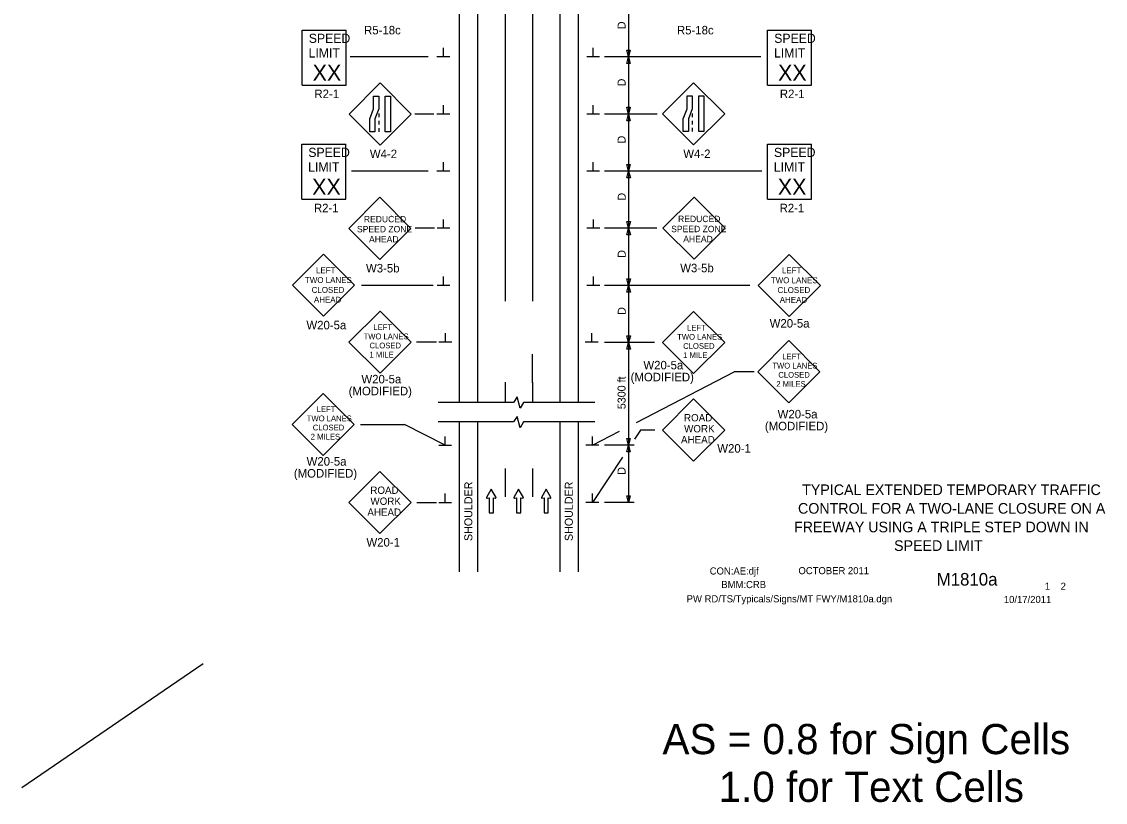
# Model space of a CAD drawing. Extents: x 16489 to 18480, y 5759 to 7026.
# Drawn here: x 16489 to 17437, y 5759 to 6442 of the extents above; entities that cross this region are included whole.
import ezdxf

# ---------------------------------------------------------------- set-up
doc = ezdxf.new("R2010")
doc.units = 0
for name, color, linetype in [('ALI_LEGAL_EX', 7, 'Continuous'), ('BORDER', 7, 'Continuous'), ('BORDER_SIGNAL_WO', 7, 'Continuous'), ('MT_SCRATCH_LEVEL_E', 7, 'Continuous'), ('PAVT_EDGE_EX', 7, 'Continuous'), ('TRAFFIC_SIGNS_PR', 7, 'Continuous'), ('TYPICAL_TEXT_DIMEN_PR', 7, 'Continuous')]:
    doc.layers.add(name, color=color, linetype=linetype)

msp = doc.modelspace()

# ---------------------------------------------------------------- linework, layer by layer
at = {"layer": 'ALI_LEGAL_EX'}
for p, q in [((16911.66, 7026.35), (16911.66, 6197.16)), ((16935.66, 7026.35), (16935.66, 6197.16)), ((16935.66, 7026.35), (16935.66, 6197.16))]:
    msp.add_line(p, q, dxfattribs=at)
for points in [[(16911.66, 6426.35), (16911.66, 6401.35)], [(16935.66, 6426.35), (16935.66, 6401.35)], [(16911.66, 6326.35), (16911.66, 6301.35)], [(16935.66, 6326.35), (16935.66, 6301.35)], [(16911.66, 6226.35), (16911.66, 6201.35)], [(16935.66, 6226.35), (16935.66, 6201.35)], [(16935.66, 6125.91), (16935.66, 6150.91)], [(16911.66, 6126.35), (16911.66, 6108.7)], [(16935.66, 6126.35), (16935.66, 6108.7)], [(16911.66, 6050.91), (16911.66, 6025.91)], [(16935.66, 6050.91), (16935.66, 6025.91)]]:
    msp.add_lwpolyline(points, dxfattribs=at)
at = {"layer": 'MT_SCRATCH_LEVEL_E'}
for p, q in [((16899.66, 6032.81), (16895.55, 6025.57)), ((16903.81, 6025.57), (16899.66, 6032.81)), ((16923.57, 6032.81), (16919.46, 6025.57)), ((16927.71, 6025.57), (16923.57, 6032.81)), ((16947.62, 6032.81), (16943.51, 6025.57)), ((16951.77, 6025.57), (16947.62, 6032.81)), ((16896.03, 6024.89), (16897.81, 6025.2)), ((16897.81, 6025.2), (16897.81, 6011.94)), ((16901.55, 6011.94), (16901.55, 6025.2)), ((16901.55, 6025.2), (16903.33, 6024.89)), ((16919.94, 6024.89), (16921.72, 6025.2)), ((16921.72, 6025.2), (16921.72, 6011.94)), ((16925.46, 6011.94), (16925.46, 6025.2)), ((16925.46, 6025.2), (16927.24, 6024.89)), ((16943.99, 6024.89), (16945.77, 6025.2)), ((16945.77, 6025.2), (16945.77, 6011.94)), ((16949.51, 6011.94), (16949.51, 6025.2)), ((16949.51, 6025.2), (16951.29, 6024.89)), ((16897.81, 6011.94), (16901.55, 6011.94)), ((16921.72, 6011.94), (16925.46, 6011.94)), ((16945.77, 6011.94), (16949.51, 6011.94))]:
    msp.add_line(p, q, dxfattribs=at)
for centre, start, end in [((16895.96, 6025.34), 150.42484, 279.96381), ((16903.4, 6025.34), 260.03619, 29.77312), ((16919.86, 6025.34), 150.42484, 279.96381), ((16927.3, 6025.34), 260.03619, 29.77312), ((16943.92, 6025.34), 150.42484, 279.96381), ((16951.36, 6025.34), 260.03619, 29.77312)]:
    msp.add_arc(centre, 0.463, start, end, dxfattribs=at)
at = {"layer": 'PAVT_EDGE_EX'}
for p, q in [((16871.66, 6926.66), (16871.66, 6108.7)), ((16887.66, 6926.66), (16887.66, 6108.7)), ((16959.66, 6926.66), (16959.66, 6108.7)), ((16975.66, 6926.66), (16975.66, 6108.7)), ((16871.66, 6091.58), (16871.66, 5960.31)), ((16887.66, 6091.58), (16887.66, 5960.31)), ((16959.66, 6091.58), (16959.66, 5960.31)), ((16975.66, 6091.58), (16975.66, 5960.31))]:
    msp.add_line(p, q, dxfattribs=at)
at = {"layer": 'TRAFFIC_SIGNS_PR'}
for p, q in [((16734.27, 6434.49), (16772.71, 6434.49)), ((16734.27, 6386.43), (16734.27, 6434.49)), ((16772.71, 6386.43), (16772.71, 6434.49)), ((17141.33, 6434.49), (17179.77, 6434.49)), ((17141.33, 6386.43), (17141.33, 6434.49)), ((17179.77, 6386.43), (17179.77, 6434.49)), ((16802.51, 6388.21), (16775.36, 6361.06)), ((16829.67, 6361.06), (16802.51, 6388.21)), ((17076.63, 6388.29), (17049.48, 6361.14)), ((17103.78, 6361.14), (17076.63, 6388.29)), ((16734.27, 6386.43), (16772.71, 6386.43)), ((17141.33, 6386.43), (17179.77, 6386.43)), ((16775.36, 6361.06), (16802.51, 6333.9)), ((16801.27, 6361.55), (16801.27, 6358.35)), ((16802.51, 6333.9), (16829.67, 6361.06)), ((17049.48, 6361.14), (17076.63, 6333.98)), ((17075.38, 6361.63), (17075.38, 6358.43)), ((17076.63, 6333.98), (17103.78, 6361.14)), ((16801.27, 6355.15), (16801.27, 6351.95)), ((17075.38, 6355.23), (17075.38, 6352.03)), ((16801.27, 6348.75), (16801.27, 6345.55)), ((17075.38, 6348.83), (17075.38, 6345.63)), ((16733.86, 6334.64), (16772.31, 6334.64)), ((16733.86, 6286.58), (16733.86, 6334.64)), ((16772.31, 6286.58), (16772.31, 6334.64)), ((17141.12, 6334.64), (17179.57, 6334.64)), ((17141.12, 6286.58), (17141.12, 6334.64)), ((17179.57, 6286.58), (17179.57, 6334.64)), ((16733.86, 6286.58), (16772.31, 6286.58)), ((16802.14, 6288.17), (16774.99, 6261.01)), ((16829.29, 6261.01), (16802.14, 6288.17)), ((17076.95, 6288.3), (17049.8, 6261.15)), ((17104.1, 6261.15), (17076.95, 6288.3)), ((17141.12, 6286.58), (17179.57, 6286.58)), ((16774.99, 6261.01), (16802.14, 6233.86)), ((16802.14, 6233.86), (16829.29, 6261.01)), ((17049.8, 6261.15), (17076.95, 6234)), ((17076.95, 6234), (17104.1, 6261.15)), ((16752.86, 6238.37), (16725.7, 6211.22)), ((16780.01, 6211.22), (16752.86, 6238.37)), ((17160.3, 6238.23), (17133.14, 6211.08)), ((17187.45, 6211.08), (17160.3, 6238.23)), ((16725.7, 6211.22), (16752.86, 6184.07)), ((16752.86, 6184.07), (16780.01, 6211.22)), ((17133.14, 6211.08), (17160.3, 6183.92)), ((17160.3, 6183.92), (17187.45, 6211.08)), ((16802.34, 6188.67), (16775.15, 6161.48)), ((16829.53, 6161.48), (16802.34, 6188.67)), ((17076.64, 6188.26), (17049.45, 6161.07)), ((17103.83, 6161.07), (17076.64, 6188.26)), ((16775.15, 6161.48), (16802.34, 6134.29)), ((16802.34, 6134.29), (16829.53, 6161.48)), ((17049.45, 6161.07), (17076.64, 6133.88)), ((17076.64, 6133.88), (17103.83, 6161.07)), ((17159.87, 6162.73), (17132.68, 6135.54)), ((17187.05, 6135.54), (17159.87, 6162.73)), ((17132.68, 6135.54), (17159.87, 6108.35)), ((17159.87, 6108.35), (17187.05, 6135.54)), ((16752.69, 6116.6), (16725.5, 6089.42)), ((16779.87, 6089.42), (16752.69, 6116.6)), ((17076.64, 6111.71), (17049.45, 6084.52)), ((17103.83, 6084.52), (17076.64, 6111.71)), ((16725.5, 6089.42), (16752.69, 6062.23)), ((16752.69, 6062.23), (16779.87, 6089.42)), ((17049.45, 6084.52), (17076.64, 6057.33)), ((17076.64, 6057.33), (17103.83, 6084.52)), ((16802.33, 6048.26), (16775.17, 6021.11)), ((16829.48, 6021.11), (16802.33, 6048.26)), ((16775.17, 6021.11), (16802.33, 5993.96)), ((16802.33, 5993.96), (16829.48, 6021.11))]:
    msp.add_line(p, q, dxfattribs=at)
for points in [[(16801.27, 6376.79), (16801.27, 6365.61), (16797.92, 6356.73), (16797.92, 6345.55), (16793.43, 6345.55), (16793.43, 6356.73), (16796.77, 6365.61), (16796.77, 6376.79)], [(16811.4, 6376.79), (16811.4, 6345.55), (16806.91, 6345.55), (16806.91, 6376.79)], [(17075.38, 6376.87), (17075.38, 6365.69), (17072.04, 6356.81), (17072.04, 6345.63), (17067.55, 6345.63), (17067.55, 6356.81), (17070.89, 6365.69), (17070.89, 6376.87)], [(17085.52, 6376.87), (17085.52, 6345.63), (17081.03, 6345.63), (17081.03, 6376.87)]]:
    msp.add_lwpolyline(points, close=True, dxfattribs=at)
at = {"layer": 'TYPICAL_TEXT_DIMEN_PR'}
for p, q in [((17019.66, 6461.07), (17019.66, 6411.07)), ((16857.78, 6411.07), (16857.78, 6418.85)), ((16988.79, 6411.07), (16988.79, 6418.85)), ((17019.66, 6411.07), (17018.09, 6416.93)), ((17018.09, 6416.93), (17019.66, 6416.93)), ((17019.66, 6416.93), (17021.23, 6416.93)), ((17021.23, 6416.93), (17019.66, 6411.07)), ((16844.35, 6411.07), (16776.36, 6411.07)), ((16863.4, 6411.07), (16852.15, 6411.07)), ((16994.41, 6411.07), (16983.16, 6411.07)), ((17026.51, 6411.07), (16998.66, 6411.07)), ((17018.09, 6405.21), (17019.66, 6411.07)), ((17019.66, 6411.07), (17019.66, 6361.07)), ((17019.66, 6411.07), (17021.23, 6405.21)), ((17135.5, 6411.07), (17026.51, 6411.07)), ((17019.66, 6405.21), (17018.09, 6405.21)), ((17021.23, 6405.21), (17019.66, 6405.21)), ((16857.78, 6361.07), (16857.78, 6368.85)), ((16988.79, 6361.07), (16988.79, 6368.85)), ((16849.5, 6361.07), (16832.91, 6361.07)), ((16863.4, 6361.07), (16852.15, 6361.07)), ((16994.41, 6361.07), (16983.16, 6361.07)), ((17026.51, 6361.07), (16998.66, 6361.07)), ((17019.66, 6361.07), (17018.09, 6366.93)), ((17018.09, 6366.93), (17019.66, 6366.93)), ((17018.09, 6355.21), (17019.66, 6361.07)), ((17019.66, 6366.93), (17021.23, 6366.93)), ((17021.23, 6366.93), (17019.66, 6361.07)), ((17019.66, 6361.07), (17019.66, 6311.07)), ((17019.66, 6361.07), (17021.23, 6355.21)), ((17044.77, 6361.07), (17026.51, 6361.07)), ((17019.66, 6355.21), (17018.09, 6355.21)), ((17021.23, 6355.21), (17019.66, 6355.21)), ((16857.78, 6311.07), (16857.78, 6318.85)), ((16988.79, 6311.07), (16988.79, 6318.85)), ((17019.66, 6311.07), (17018.09, 6316.93)), ((17018.09, 6316.93), (17019.66, 6316.93)), ((17019.66, 6316.93), (17021.23, 6316.93)), ((17021.23, 6316.93), (17019.66, 6311.07)), ((16844.35, 6311.07), (16777.31, 6311.07)), ((16863.4, 6311.07), (16852.15, 6311.07)), ((16994.41, 6311.07), (16983.16, 6311.07)), ((17026.51, 6311.07), (16998.66, 6311.07)), ((17018.23, 6305.21), (17019.8, 6311.07)), ((17019.8, 6305.21), (17018.23, 6305.21)), ((17019.8, 6311.07), (17019.8, 6261.07)), ((17019.8, 6311.07), (17021.37, 6305.21)), ((17021.37, 6305.21), (17019.8, 6305.21)), ((17136.37, 6311.07), (17026.51, 6311.07)), ((16857.92, 6261.07), (16857.92, 6268.85)), ((16988.93, 6261.07), (16988.93, 6268.85)), ((17019.8, 6261.07), (17018.23, 6266.93)), ((17018.23, 6266.93), (17019.8, 6266.93)), ((17019.8, 6266.93), (17021.37, 6266.93)), ((17021.37, 6266.93), (17019.8, 6261.07)), ((16849.97, 6261.07), (16833.23, 6261.07)), ((16863.54, 6261.07), (16852.29, 6261.07)), ((16994.55, 6261.07), (16983.3, 6261.07)), ((17026.51, 6261.07), (16998.8, 6261.07)), ((17018.23, 6255.21), (17019.8, 6261.07)), ((17019.8, 6255.21), (17018.23, 6255.21)), ((17019.8, 6261.07), (17019.8, 6211.07)), ((17019.8, 6261.07), (17021.37, 6255.21)), ((17021.37, 6255.21), (17019.8, 6255.21)), ((17044.48, 6261.07), (17026.51, 6261.07)), ((16857.92, 6211.07), (16857.92, 6218.85)), ((16988.93, 6211.07), (16988.93, 6218.85)), ((16848.7, 6211.07), (16786.08, 6211.07)), ((16863.54, 6211.07), (16852.29, 6211.07)), ((16994.55, 6211.07), (16983.3, 6211.07)), ((17125.87, 6211.07), (16998.8, 6211.07)), ((17019.8, 6211.07), (17018.23, 6216.93)), ((17018.23, 6216.93), (17019.8, 6216.93)), ((17018.23, 6205.21), (17019.8, 6211.07)), ((17019.8, 6216.93), (17021.37, 6216.93)), ((17021.37, 6216.93), (17019.8, 6211.07)), ((17019.8, 6211.07), (17019.8, 6161.07)), ((17019.8, 6211.07), (17021.37, 6205.21)), ((17019.8, 6205.21), (17018.23, 6205.21)), ((17021.37, 6205.21), (17019.8, 6205.21)), ((17019.66, 6171.14), (17019.66, 6071.14)), ((16851.77, 6161.4), (16834.37, 6161.4)), ((16865.09, 6161.4), (16853.84, 6161.4)), ((16859.47, 6161.4), (16859.47, 6169.18)), ((16993.15, 6161.4), (16981.9, 6161.4)), ((16987.53, 6161.4), (16987.53, 6169.18)), ((17042.32, 6161.07), (16998.59, 6161.07)), ((17019.8, 6161.07), (17018.23, 6166.93)), ((17018.23, 6166.93), (17019.8, 6166.93)), ((17018.23, 6155.21), (17019.8, 6161.07)), ((17019.8, 6166.93), (17021.37, 6166.93)), ((17021.37, 6166.93), (17019.8, 6161.07)), ((17019.8, 6161.07), (17021.37, 6155.21)), ((17019.8, 6155.21), (17018.23, 6155.21)), ((17021.37, 6155.21), (17019.8, 6155.21)), ((17026.75, 6091.21), (17112.22, 6135.54)), ((17129.62, 6135.54), (17112.22, 6135.54)), ((16922.27, 6113.5), (16919.01, 6108.7)), ((16925.01, 6103.57), (16922.27, 6113.5)), ((16919.01, 6108.7), (16853.07, 6108.7)), ((16927.75, 6108.7), (16925.01, 6103.57)), ((16990.08, 6108.7), (16927.75, 6108.7)), ((16922.27, 6096.37), (16919.01, 6091.57)), ((16925.01, 6086.43), (16922.27, 6096.37)), ((16785.41, 6089.41), (16823.65, 6089.41)), ((16859.29, 6071.14), (16823.65, 6089.41)), ((16919.01, 6091.57), (16853.07, 6091.57)), ((16927.75, 6091.57), (16925.01, 6086.43)), ((16990.08, 6091.57), (16927.75, 6091.57)), ((17030.22, 6084.52), (17024.97, 6076.64)), ((17042.77, 6084.52), (17030.22, 6084.52)), ((16859.29, 6071.14), (16859.29, 6078.93)), ((16988.04, 6071.14), (17011.86, 6083.5)), ((16988.04, 6071.14), (16988.04, 6078.93)), ((17019.66, 6071.14), (17018.09, 6077.01)), ((17018.09, 6077.01), (17019.66, 6077.01)), ((17019.66, 6077.01), (17021.24, 6077.01)), ((17021.24, 6077.01), (17019.66, 6071.14)), ((16853.66, 6071.14), (16864.91, 6071.14)), ((16993.66, 6071.14), (16982.41, 6071.14)), ((17024.66, 6071.14), (16998.66, 6071.14)), ((17018.09, 6065.28), (17019.66, 6071.14)), ((17019.66, 6071.14), (17019.66, 6021.14)), ((17019.66, 6071.14), (17021.24, 6065.28)), ((17014.44, 6060.82), (16988.04, 6021.14)), ((17019.66, 6065.28), (17018.09, 6065.28)), ((17021.24, 6065.28), (17019.66, 6065.28)), ((16859.29, 6021.14), (16859.29, 6028.93)), ((16988.04, 6021.14), (16988.04, 6028.93)), ((16834.65, 6021.14), (16851.77, 6021.14)), ((16853.66, 6021.14), (16864.91, 6021.14)), ((16993.66, 6021.14), (16982.41, 6021.14)), ((17024.66, 6021.14), (16998.66, 6021.14)), ((17019.66, 6021.14), (17018.09, 6027.01)), ((17018.09, 6027.01), (17019.66, 6027.01)), ((17019.66, 6027.01), (17021.24, 6027.01)), ((17021.24, 6027.01), (17019.66, 6021.14)), ((16647.75, 5880), (16488.95, 5771.23))]:
    msp.add_line(p, q, dxfattribs=at)

# ---------------------------------------------------------------- texts
at = {"layer": 'BORDER'}
for s, p in [('TYPICAL EXTENDED TEMPORARY TRAFFIC', (17171.54, 6027.6)), ('CONTROL FOR A TWO-LANE CLOSURE ON A', (17167.92, 6011.3)), ('FREEWAY USING A TRIPLE STEP DOWN IN ', (17164.42, 5995)), ('SPEED LIMIT', (17251.92, 5978.7))]:
    msp.add_text(s, height=9.3, dxfattribs=at).set_placement(p)
at = {"layer": 'BORDER_SIGNAL_WO'}
for s, height, p in [('CON:AE:djf  ', 6.2, (17090.69, 5958.06)), ('    OCTOBER 2011', 6.2, (17159.08, 5958.34)), ('BMM:CRB', 6.2, (17100.81, 5946.17)), ('    M1810a   ', 11, (17272.86, 5948.38)), (' 1    2 ', 6.2, (17381.45, 5944.7)), ('PW RD/TS/Typicals/Signs/MT FWY/M1810a.dgn      ', 6.2, (17070.55, 5933.71)), ('10/17/2011', 6.2, (17347.93, 5933.13)), ('AS = 0.8 for Sign Cells', 26.4241, (17049.39, 5800.83)), ('     1.0 for Text Cells', 26.4241, (17049.39, 5759.05))]:
    msp.add_text(s, height=height, dxfattribs=at).set_placement(p)
at = {"layer": 'TRAFFIC_SIGNS_PR'}
for s, height, p in [('R5-18c', 7.44, (16788.43, 6430.75)), ('R5-18c', 7.44, (17062.04, 6430.75)), ('SPEED', 8.01, (16740.04, 6423.33)), ('SPEED', 8.01, (17147.1, 6423.33)), ('LIMIT', 8.01, (16739.88, 6410.52)), ('LIMIT', 8.01, (17146.94, 6410.52)), ('XX', 14.048, (16743.39, 6390.19)), ('XX', 14.048, (17150.45, 6390.19)), ('R2-1', 7.449, (16744.96, 6374.97)), ('R2-1', 7.449, (17152.02, 6374.97)), ('SPEED', 8.01, (16739.64, 6323.48)), ('SPEED', 8.01, (17146.89, 6323.48)), ('W4-2', 7.44, (16793.47, 6322.46)), ('W4-2', 7.44, (17067.59, 6322.54)), ('LIMIT', 8.01, (16739.48, 6310.67)), ('LIMIT', 8.01, (17146.73, 6310.67)), ('XX', 14.048, (16742.99, 6290.34)), ('XX', 14.048, (17150.24, 6290.34)), ('R2-1', 7.449, (16744.55, 6275.12)), ('R2-1', 7.449, (17151.81, 6275.12)), ('REDUCED', 5.6, (16788.2, 6266.32)), ('REDUCED', 5.6, (17063.01, 6266.46)), ('SPEED ZONE', 5.6, (16782.19, 6257.52)), ('SPEED ZONE', 5.6, (17057, 6257.66)), ('AHEAD', 5.6, (16792.75, 6248.72)), ('AHEAD', 5.6, (17067.56, 6248.86)), ('LEFT', 5.2, (16746.39, 6221.75)), ('W3-5b', 7.44, (16790.09, 6222.42)), ('W3-5b', 7.44, (17064.9, 6222.56)), ('LEFT', 5.2, (17153.83, 6221.61)), ('TWO LANES', 5.2, (16736.72, 6213.15)), ('TWO LANES', 5.2, (17144.16, 6213.01)), ('CLOSED', 5.2, (16742.57, 6204.55)), ('CLOSED', 5.2, (17150.01, 6204.41)), ('AHEAD', 5.2, (16744.52, 6195.95)), ('AHEAD', 5.2, (17151.95, 6195.81)), ('W20-5a', 7.44, (16738, 6172.63)), ('W20-5a', 7.44, (17143.13, 6174.18)), ('LEFT', 5.006, (16796.58, 6171.97)), ('LEFT', 5.006, (17070.88, 6171.56)), ('TWO LANES', 5.006, (16787.93, 6163.96)), ('CLOSED', 5.006, (16793.16, 6155.96)), ('TWO LANES', 5.006, (17062.23, 6163.55)), ('CLOSED', 5.006, (17067.46, 6155.55)), ('1 MILE', 5.006, (16793.16, 6147.95)), ('1 MILE', 5.006, (17067.46, 6147.54)), ('LEFT', 5.006, (17154.11, 6146.33)), ('W20-5a', 7.449, (17032.7, 6137.58)), ('TWO LANES', 5.006, (17145.46, 6138.32)), ('W20-5a', 7.449, (16786.09, 6125.33)), ('(MODIFIED)', 7.449, (17021.54, 6127.13)), ('CLOSED', 5.006, (17150.69, 6130.32)), ('(MODIFIED)', 7.449, (16774.93, 6114.88)), ('2 MILES', 5.006, (17148.94, 6122.31)), ('LEFT', 5.006, (16746.93, 6100.21)), ('TWO LANES', 5.006, (16738.28, 6092.2)), ('ROAD', 6.408, (17068.17, 6092.07)), ('W20-5a', 7.449, (17150.09, 6094.69)), ('CLOSED', 5.006, (16743.51, 6084.19)), ('WORK', 6.408, (17068.28, 6082.46)), ('(MODIFIED)', 7.449, (17138.93, 6084.24)), ('2 MILES', 5.006, (16741.76, 6076.19)), ('AHEAD', 6.408, (17065.59, 6072.84)), ('W20-1', 7.449, (17097.32, 6064.73)), ('W20-5a', 7.449, (16738.14, 6053.35)), ('(MODIFIED)', 7.449, (16726.98, 6042.9)), ('ROAD', 6.4, (16793.87, 6028.64)), ('WORK', 6.4, (16793.98, 6019.04)), ('AHEAD', 6.4, (16791.29, 6009.44)), ('W20-1', 7.44, (16790.5, 5982.52))]:
    msp.add_text(s, height=height, dxfattribs=at).set_placement(p)
at = {"layer": 'TYPICAL_TEXT_DIMEN_PR'}
for s, p in [('D', (17017.11, 6435.29)), ('D', (17017.11, 6385.29)), ('D', (17017.11, 6335.29)), ('D', (17017.24, 6285.29)), ('D', (17017.24, 6235.29)), ('D', (17017.24, 6185.29)), ('5300 ft', (17017.11, 6102.75)), ('D', (17017.11, 6045.36)), ('SHOULDER', (16883.08, 5987.36)), ('SHOULDER', (16970.94, 5987.36))]:
    msp.add_text(s, height=7, rotation=90, dxfattribs=at).set_placement(p)

doc.saveas('drawing.dxf')
